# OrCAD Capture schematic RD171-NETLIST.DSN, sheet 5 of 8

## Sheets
5 4: size A3
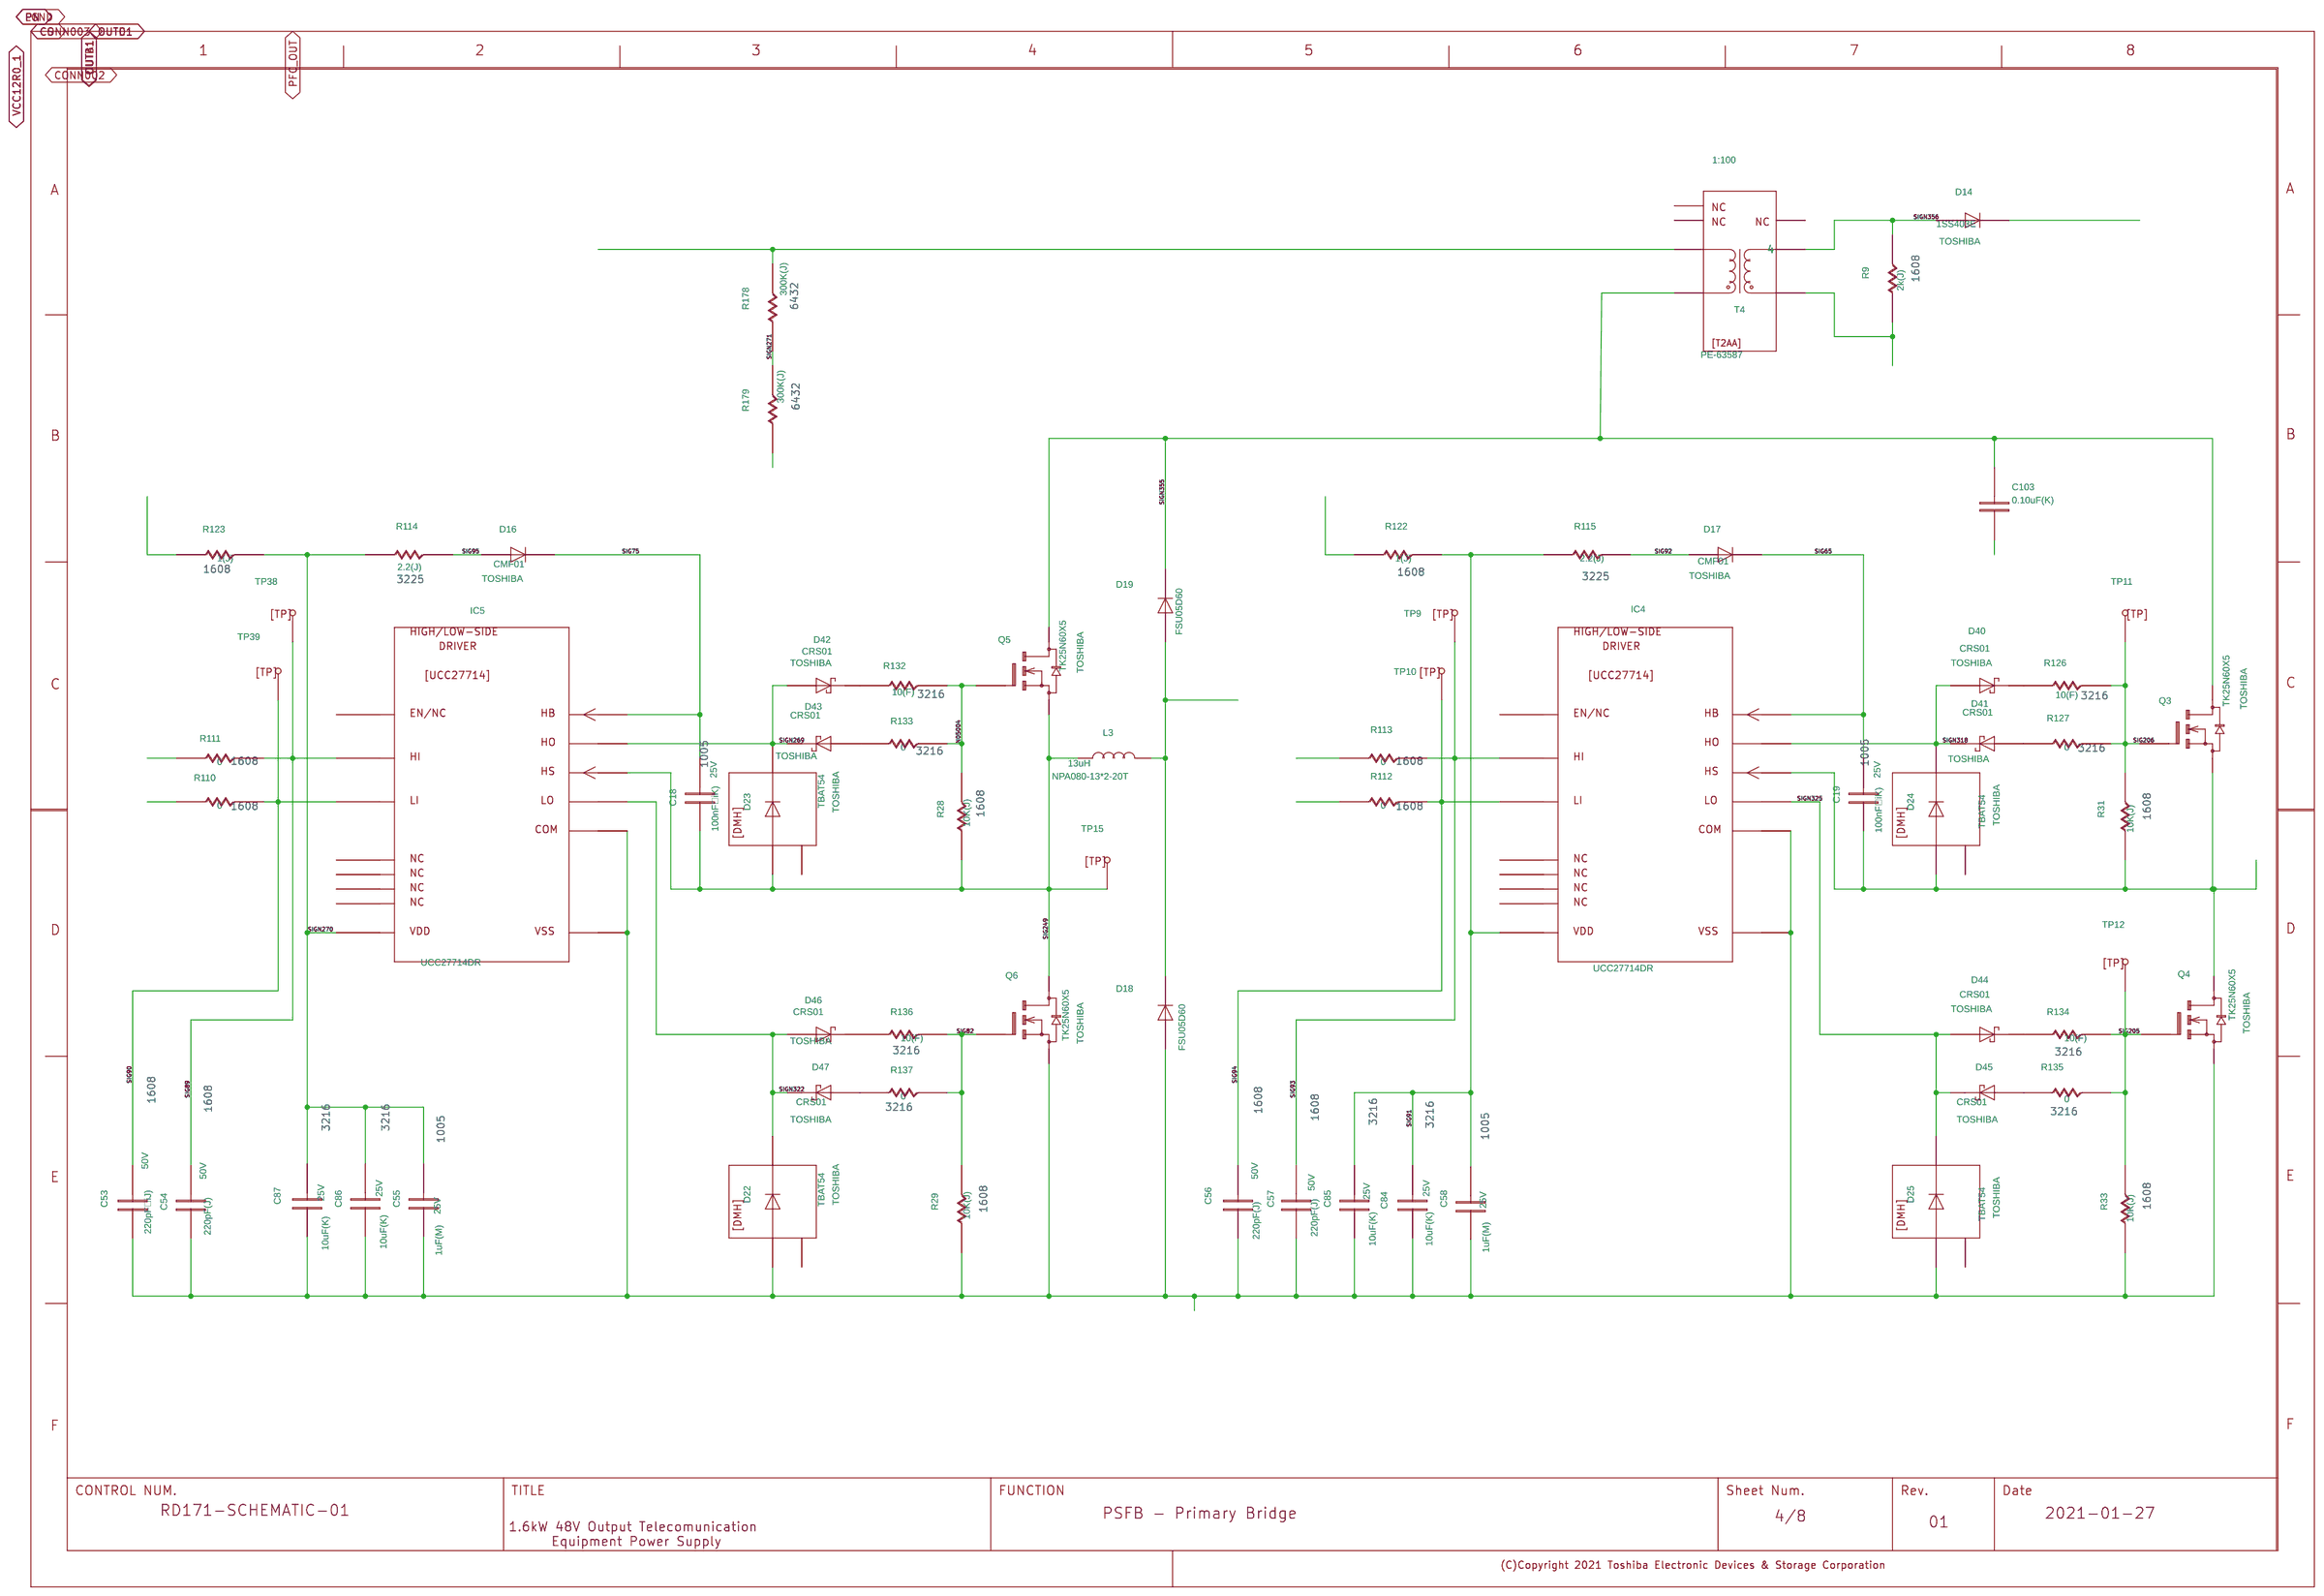
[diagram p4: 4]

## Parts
C18  100nF
C19  100nF
C53  220pF
C54  220pF
C55  1uF
C56  220pF
C57  220pF
C58  1uF
C84  10uF
C85  10uF
C86  10uF
C87  10uF
C103  0.10ƒÊF
D14  D14  [1SS403E]
D16  D16  [CMF01]
D17  D17  [CMF01]
D18  D1  [TRS8E65F]
D19  D1  [TRS8E65F]
D22  D22  [TBAT54]
D23  D23  [TBAT54]
D24  D24  [TBAT54]
D25  D25  [TBAT54]
D40  D40  [CRS01]
D41  D41  [CRS01]
D42  D42  [CRS01]
D43  D43  [CRS01]
D44  D44  [CRS01]
D45  D45  [CRS01]
D46  D46  [CRS01]
D47  D47  [CRS01]
IC4  IC4  [UCC27714DR]
IC5  IC5  [UCC27714DR]
L3  8.4uH  [NPA080-14*2-16T]
Q3  Q3  [TK25N60X5]
Q4  Q4  [TK25N60X5]
Q5  Q5  [TK25N60X5]
Q6  Q6  [TK25N60X5]
R9  2k
R28  10k
R29  10k
R31  10k
R33  10k
R110  0
R111  0
R112  0
R113  0
R114  2.2
R115  2.2
R122  1
R123  1
R126  10
R127  0
R132  10
R133  0
R134  10
R135  0
R136  10
R137  0
R178  300k
R179  300k
T4  1:100  [PE-63587NL]
TP9  TP9  [HK-2-S]
TP10  TP10  [HK-2-S]
TP11  TP11  [HK-2-S]
TP12  TP12  [HK-2-S]
TP15  TP15  [HK-2-S]
TP38  TP38  [HK-2-S]
TP39  TP39  [HK-2-S]
U?#4  WAKU_DEF100

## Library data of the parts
C18 = C: ADSCNVFLAG: ON; ADSCOMPONENTNAME: C_1005; ADSMODELNAME: s_C1005JB1C224KT; CAPACITANCETOLE: K; CDMASTERCADCELG: KC0005; CHIPSIZE: 1005; COMP: PRT_52; COMPONENTNAME: C_C.Normal_package; FNLEADFREETHET1GT2GMCTH1: N_N_N; FUNCTION: C_C.Normal_package; GCOUNT: 1; ICX_PART_MODEL: CON_220N; INSTANCENAME: INS4234; MAKER: TDK; MAXGCOUNT: 1; NOMINALCAPACITA: 220n; OUMECLASSIFICATION: ƒZƒ‰ƒ~ƒbƒNƒRƒ“ƒfƒ“ƒT; OUMEMAKER: TDK ‚s‚c‚j; OUMEMAKERKATAMEI: C1005JB1C224KT; PARTNAME: Chip1005_GS_2; QUADMODEL: CON_220N; RATEDVOLTAGE: 16; SIZECODESMD: 1005; SQ_PART_MODEL: CON_220N; TEMPCHARACTERI2: B; VAL1: 100nFiK); VAL2: 25V; VAL3: C1005X7R1E104K050BB
C19 = C: ADSMODELNAME: s_C1005JB1C224KT; CAPACITANCETOLE: K; CDMASTERCADCELG: KC0005; CHIPSIZE: 1005; COMP: PRT_52; COMPONENTNAME: C_C.Normal_package; FNLEADFREETHET1GT2GMCTH1: N_N_N; FUNCTION: C_C.Normal_package; GCOUNT: 1; INSTANCENAME: INS4196; MAKER: TDK; MAXGCOUNT: 1; NOMINALCAPACITA: 220n; OUMECLASSIFICATION: ƒZƒ‰ƒ~ƒbƒNƒRƒ“ƒfƒ“ƒT; OUMEMAKER: TDK ‚s‚c‚j; OUMEMAKERKATAMEI: C1005JB1C224KT; PARTNAME: Chip1005_GS_2; QUADMODEL: CON_220N; RATEDVOLTAGE: 16; SIZECODESMD: 1005; TEMPCHARACTERI2: B; VAL1: 100nFiK); VAL2: 25V; VAL3: C1005X7R1E104K050BB
C53 = C: ADSMODELNAME: s_GCM1885C1H221JA16D; CAPACITANCETOLE: J; CDMASTERCADCELG: KC0008; CHIPSIZE: 1608; COMP: PRT_48; COMPONENTNAME: C_C.Normal_package; FNLEADFREETHET1GT2GMCTH1: N_N_N; FUNCTION: C_C.Normal_package; GCOUNT: 1; INSTANCENAME: INS4564; MAKER: MURATA; MAXGCOUNT: 1; NOMINALCAPACITA: 220p; OUMECLASSIFICATION: ƒZƒ‰ƒ~ƒbƒNƒRƒ“ƒfƒ“ƒT; OUMEMAKER: MRT ºc»ì; OUMEMAKERKATAMEI: GCM1885C1H221JA16D; PARTNAME: Chip1608_GS_1; PMPRODUCTSTYPEG: DME; QUADMODEL: CON_220P; RATEDVOLTAGE: 50; SIZECODESMD: 1608; VAL1: 220pFiJ); VAL2: 50V; VAL3: GRM1885C1H221JA01D
C54 = C: ADSMODELNAME: s_GCM1885C1H221JA16D; CAPACITANCETOLE: J; CDMASTERCADCELG: KC0008; CHIPSIZE: 1608; COMP: PRT_48; COMPONENTNAME: C_C.Normal_package; FNLEADFREETHET1GT2GMCTH1: N_N_N; FUNCTION: C_C.Normal_package; GCOUNT: 1; INSTANCENAME: INS4576; MAKER: MURATA; MAXGCOUNT: 1; NOMINALCAPACITA: 220p; OUMECLASSIFICATION: ƒZƒ‰ƒ~ƒbƒNƒRƒ“ƒfƒ“ƒT; OUMEMAKER: MRT ºc»ì; OUMEMAKERKATAMEI: GCM1885C1H221JA16D; PARTNAME: Chip1608_GS_1; PMPRODUCTSTYPEG: DME; QUADMODEL: CON_220P; RATEDVOLTAGE: 50; SIZECODESMD: 1608; VAL1: 220pF(J); VAL2: 50V; VAL3: GRM1885C1H221JA01D
C55 = C: ADSCNVFLAG: ON; ADSCOMPONENTNAME: C_1005; ADSMODELNAME: s_GRM155R61A225KE95D; CAPACITANCETOLE: K; CDMASTERCADCELG: KC0005; CHIPSIZE: 1005; COMP: PRT_52; COMPONENTNAME: C_C.Normal_package; FNLEADFREETHET1GT2GMCTH1: N_N_N; FUNCTION: C_C.Normal_package; GCOUNT: 1; ICX_PART_MODEL: CON_2.2U; INSTANCENAME: INS4176; MAKER: TDK; MAXGCOUNT: 1; NOMINALCAPACITA: 2.2u; OUMECLASSIFICATION: ƒZƒ‰ƒ~ƒbƒNƒRƒ“ƒfƒ“ƒT; OUMEMAKER: MRT ºc»ì; OUMEMAKERKATAMEI: GRM155R61A225KE95D; PARTNAME: Chip1005_GS_2; PMPRODUCTSTYPEG: HD1; QUADMODEL: CON_2.2U; RATEDVOLTAGE: 10; SIZECODESMD: 1005; SQ_PART_MODEL: CON_2.2U; VAL1: 1uF(M); VAL2: 25V; VAL3: C1005X5R1E105M050BC
C56 = C: ADSMODELNAME: s_GCM1885C1H221JA16D; CAPACITANCETOLE: J; CDMASTERCADCELG: KC0008; CHIPSIZE: 1608; COMP: PRT_48; COMPONENTNAME: C_C.Normal_package; FNLEADFREETHET1GT2GMCTH1: N_N_N; FUNCTION: C_C.Normal_package; GCOUNT: 1; INSTANCENAME: INS4452; MAKER: MURATA; MAXGCOUNT: 1; NOMINALCAPACITA: 220p; OUMECLASSIFICATION: ƒZƒ‰ƒ~ƒbƒNƒRƒ“ƒfƒ“ƒT; OUMEMAKER: MRT ºc»ì; OUMEMAKERKATAMEI: GCM1885C1H221JA16D; PARTNAME: Chip1608_GS_1; PMPRODUCTSTYPEG: DME; QUADMODEL: CON_220P; RATEDVOLTAGE: 50; SIZECODESMD: 1608; VAL1: 220pF(J); VAL2: 50V; VAL3: GRM1885C1H221JA01D
C57 = C: ADSMODELNAME: s_GCM1885C1H221JA16D; CAPACITANCETOLE: J; CDMASTERCADCELG: KC0008; CHIPSIZE: 1608; COMP: PRT_48; COMPONENTNAME: C_C.Normal_package; FNLEADFREETHET1GT2GMCTH1: N_N_N; FUNCTION: C_C.Normal_package; GCOUNT: 1; INSTANCENAME: INS4440; MAKER: MURATA; MAXGCOUNT: 1; NOMINALCAPACITA: 220p; OUMECLASSIFICATION: ƒZƒ‰ƒ~ƒbƒNƒRƒ“ƒfƒ“ƒT; OUMEMAKER: MRT ºc»ì; OUMEMAKERKATAMEI: GCM1885C1H221JA16D; PARTNAME: Chip1608_GS_1; PMPRODUCTSTYPEG: DME; QUADMODEL: CON_220P; RATEDVOLTAGE: 50; SIZECODESMD: 1608; VAL1: 220pF(J); VAL2: 50V; VAL3: GRM1885C1H221JA01D
C58 = C: ADSMODELNAME: s_GRM155R61A225KE95D; CAPACITANCETOLE: K; CDMASTERCADCELG: KC0005; CHIPSIZE: 1005; COMP: PRT_52; COMPONENTNAME: C_C.Normal_package; FNLEADFREETHET1GT2GMCTH1: N_N_N; FUNCTION: C_C.Normal_package; GCOUNT: 1; INSTANCENAME: INS4186; MAKER: TDK; MAXGCOUNT: 1; NOMINALCAPACITA: 2.2u; OUMECLASSIFICATION: ƒZƒ‰ƒ~ƒbƒNƒRƒ“ƒfƒ“ƒT; OUMEMAKER: MRT ºc»ì; OUMEMAKERKATAMEI: GRM155R61A225KE95D; PARTNAME: Chip1005_GS_2; PMPRODUCTSTYPEG: HD1; QUADMODEL: CON_2.2U; RATEDVOLTAGE: 10; SIZECODESMD: 1005; VAL1: 1uF(M); VAL2: 25V; VAL3: C1005X5R1E105M050BC
C84 = C: ADSMODELNAME: s_TMK316LD106KL_T; CAPACITANCETOLE: K; CDMASTERCADCELG: KC0014; CHIPSIZE: 3216; COMP: PRT_46; COMPONENTNAME: C_C.Normal_package; FNLEADFREETHET1GT2GMCTH1: N_N_N; FUNCTION: C_C.Normal_package; GCOUNT: 1; INSTANCENAME: INS4474; MAKER: TAIYO YUDEN; MAXGCOUNT: 1; NOMINALCAPACITA: 10u; OUMECLASSIFICATION: ƒZƒ‰ƒ~ƒbƒNƒRƒ“ƒfƒ“ƒT; OUMEMAKER: TYD ‘¾—z—U“d; OUMEMAKERKATAMEI: TMK316LD106KL-T; PARTNAME: Chip3216_GS_1; QUADMODEL: CON_10U; RATEDVOLTAGE: 25; SIZECODESMD: 3216; VAL1: 10uF(K); VAL2: 25V; VAL3: TMK316BJ106KL-T
C85 = C: ADSMODELNAME: s_TMK316LD106KL_T; CAPACITANCETOLE: K; CDMASTERCADCELG: KC0014; CHIPSIZE: 3216; COMP: PRT_46; COMPONENTNAME: C_C.Normal_package; FNLEADFREETHET1GT2GMCTH1: N_N_N; FUNCTION: C_C.Normal_package; GCOUNT: 1; INSTANCENAME: INS4464; MAKER: TAIYO YUDEN; MAXGCOUNT: 1; NOMINALCAPACITA: 10u; OUMECLASSIFICATION: ƒZƒ‰ƒ~ƒbƒNƒRƒ“ƒfƒ“ƒT; OUMEMAKER: TYD ‘¾—z—U“d; OUMEMAKERKATAMEI: TMK316LD106KL-T; PARTNAME: Chip3216_GS_1; QUADMODEL: CON_10U; RATEDVOLTAGE: 25; SIZECODESMD: 3216; VAL1: 10uF(K); VAL2: 25V; VAL3: TMK316BJ106KL-T
C86 = C: ADSMODELNAME: s_TMK316LD106KL_T; CAPACITANCETOLE: K; CDMASTERCADCELG: KC0014; CHIPSIZE: 3216; COMP: PRT_46; COMPONENTNAME: C_C.Normal_package; FNLEADFREETHET1GT2GMCTH1: N_N_N; FUNCTION: C_C.Normal_package; GCOUNT: 1; INSTANCENAME: INS4598; MAKER: TAIYO YUDEN; MAXGCOUNT: 1; NOMINALCAPACITA: 10u; OUMECLASSIFICATION: ƒZƒ‰ƒ~ƒbƒNƒRƒ“ƒfƒ“ƒT; OUMEMAKER: TYD ‘¾—z—U“d; OUMEMAKERKATAMEI: TMK316LD106KL-T; PARTNAME: Chip3216_GS_1; QUADMODEL: CON_10U; RATEDVOLTAGE: 25; SIZECODESMD: 3216; VAL1: 10uF(K); VAL2: 25V; VAL3: TMK316BJ106KL-T
C87 = C: ADSMODELNAME: s_TMK316LD106KL_T; CAPACITANCETOLE: K; CDMASTERCADCELG: KC0014; CHIPSIZE: 3216; COMP: PRT_46; COMPONENTNAME: C_C.Normal_package; FNLEADFREETHET1GT2GMCTH1: N_N_N; FUNCTION: C_C.Normal_package; GCOUNT: 1; INSTANCENAME: INS4588; MAKER: TAIYO YUDEN; MAXGCOUNT: 1; NOMINALCAPACITA: 10u; OUMECLASSIFICATION: ƒZƒ‰ƒ~ƒbƒNƒRƒ“ƒfƒ“ƒT; OUMEMAKER: TYD ‘¾—z—U“d; OUMEMAKERKATAMEI: TMK316LD106KL-T; PARTNAME: Chip3216_GS_1; QUADMODEL: CON_10U; RATEDVOLTAGE: 25; SIZECODESMD: 3216; VAL1: 10uF(K); VAL2: 25V; VAL3: TMK316BJ106KL-T
C103 = RDER72J104K4K1H03B_0: COMPONENTNAME: RDER72J104K4K1H03B_0_RDER72J104K4K1H03B_0; INSTANCENAME: INS16960092; PARTNAME: RDER72J104_MU; VAL1: 0.10uF(K)
D14 = D: ADSMODELNAME: s_1SS352_TPH3_F_1_1E1A; CDMASTERCADCELG: D81022; COMP: PRT_27; COMPONENTNAME: D_D.Normal_package; FNLEADFREETHET1GT2GMCTH1: N_N_N; FORWARDVOLTAGEM: 0; FUNCTION: D_D.Normal_package; GCOUNT: 1; INSTANCENAME: INS4272; MAKER: TOSHIBA; MAXAVERAGEFORWA: 0; MAXGCOUNT: 1; MAXREPETITIVEPE: 0; MAXREVERSEVOLTA: 80; MOUNTINGFORMSMD: SMD; OUMECLASSIFICATION: ¬M_CI[h; OUMEMAKER: TSB “ŒŽÅ; OUMEMAKERKATAMEI: 1SS352(TPH3,F)1-1E1A; PARTNAME: 1SS403E_TS_B; PEAKFORWARDVOLT: 0; REVERSECURRENT: 0; USERCOMPTEXT3: TOSHIBA; ZENERVOLTAGEMAX: 0; ZENERVOLTAGEMIN: 0
D16 = D: ADSMODELNAME: s_MURS220T3G; CDMASTERCADCELG: DD924D; COMP: PRT_14; COMPONENTNAME: D_D.Normal_package; FNLEADFREETHET1GT2GMCTH1: 3_0_N; FORWARDVOLTAGEM: 0; FUNCTION: D_D.Normal_package; GCOUNT: 1; INSTANCENAME: INS4130; MAKER: TOSHIBA; MAXAVERAGEFORWA: 2; MAXGCOUNT: 1; MAXREPETITIVEPE: 200; MAXREVERSEVOLTA: 0; MOUNTINGFORMSMD: SMD; OUMECLASSIFICATION: êÊ®¬fq; OUMEMAKER: ONS IZ~R_N^[; OUMEMAKERKATAMEI: MURS220T3G; PARTNAME: CMF01_TS_B; PEAKFORWARDVOLT: 770m; PMPRODUCTSTYPEG: PJ1; REVERSECURRENT: 50u; USERCOMPTEXT3: TOSHIBA; ZENERVOLTAGEMAX: 0; ZENERVOLTAGEMIN: 0
D17 = D: ADSMODELNAME: s_MURS220T3G; CDMASTERCADCELG: DD924D; COMP: PRT_14; COMPONENTNAME: D_D.Normal_package; FNLEADFREETHET1GT2GMCTH1: 3_0_N; FORWARDVOLTAGEM: 0; FUNCTION: D_D.Normal_package; GCOUNT: 1; INSTANCENAME: INS3988; MAKER: TOSHIBA; MAXAVERAGEFORWA: 2; MAXGCOUNT: 1; MAXREPETITIVEPE: 200; MAXREVERSEVOLTA: 0; MOUNTINGFORMSMD: SMD; OUMECLASSIFICATION: êÊ®¬fq; OUMEMAKER: ONS IZ~R_N^[; OUMEMAKERKATAMEI: MURS220T3G; PARTNAME: CMF01_TS_B; PEAKFORWARDVOLT: 770m; PMPRODUCTSTYPEG: PJ1; REVERSECURRENT: 50u; USERCOMPTEXT3: TOSHIBA; ZENERVOLTAGEMAX: 0; ZENERVOLTAGEMIN: 0
D18 = D: ADSMODELNAME: s_FSU05D60; CDMASTERCADCELG: DCR071; COMP: PRT_12; COMPONENTNAME: D_D.Normal_package; FNLEADFREETHET1GT2GMCTH1: N_N_N; FORWARDVOLTAGEM: 0; FUNCTION: D_D.Normal_package; GCOUNT: 1; INSTANCENAME: INS16993764; MAKER: TOSHIBA; MAXAVERAGEFORWA: 0; MAXGCOUNT: 1; MAXREPETITIVEPE: 0; MAXREVERSEVOLTA: 100; MOUNTINGFORMSMD: DIP; OUMECLASSIFICATION: ¬M_CI[h; OUMEMAKER: ROH [; OUMEMAKERKATAMEI: FSU05D60; PARTNAME: FSU05D60_KC; PEAKFORWARDVOLT: 0; REVERSECURRENT: 0; USERCOMPTEXT3: KYOCERA; VAL3: FSU05D60; ZENERVOLTAGEMAX: 0; ZENERVOLTAGEMIN: 0
D19 = D: ADSMODELNAME: s_FSU05D60; CDMASTERCADCELG: DCR071; COMP: PRT_12; COMPONENTNAME: D_D.Normal_package; FNLEADFREETHET1GT2GMCTH1: N_N_N; FORWARDVOLTAGEM: 0; FUNCTION: D_D.Normal_package; GCOUNT: 1; INSTANCENAME: INS16993843; MAKER: TOSHIBA; MAXAVERAGEFORWA: 0; MAXGCOUNT: 1; MAXREPETITIVEPE: 0; MAXREVERSEVOLTA: 100; MOUNTINGFORMSMD: DIP; OUMECLASSIFICATION: ¬M_CI[h; OUMEMAKER: ROH [; OUMEMAKERKATAMEI: FSU05D60; PARTNAME: FSU05D60_KC; PEAKFORWARDVOLT: 0; REVERSECURRENT: 0; USERCOMPTEXT3: KYOCERA; VAL3: FSU05D60; ZENERVOLTAGEMAX: 0; ZENERVOLTAGEMIN: 0
D22 = DMH: COMP: PRT_25; COMPONENTNAME: DMH_DMH.Normal_package; FUNCTION: DMH_DMH.Normal_package; INSTANCENAME: INS4258; MAKER: TOSHIBA; PARTNAME: TBAT54_TS_B; USERCOMPTEXT3: TOSHIBA
D23 = DMH: COMP: PRT_25; COMPONENTNAME: DMH_DMH.Normal_package; FUNCTION: DMH_DMH.Normal_package; INSTANCENAME: INS4244; MAKER: TOSHIBA; PARTNAME: TBAT54_TS_B; USERCOMPTEXT3: TOSHIBA
D24 = DMH: COMP: PRT_25; COMPONENTNAME: DMH_DMH.Normal_package; FUNCTION: DMH_DMH.Normal_package; INSTANCENAME: INS4220; MAKER: TOSHIBA; PARTNAME: TBAT54_TS_B; USERCOMPTEXT3: TOSHIBA
D25 = DMH: COMP: PRT_25; COMPONENTNAME: DMH_DMH.Normal_package; FUNCTION: DMH_DMH.Normal_package; INSTANCENAME: INS4206; MAKER: TOSHIBA; PARTNAME: TBAT54_TS_B; USERCOMPTEXT3: TOSHIBA
D40 = SBD: COMP: PRT_11; COMPONENTNAME: SBD_SBD.Normal_package; FUNCTION: SBD_SBD.Normal_package; INSTANCENAME: INS4304; MAKER: TOSHIBA; PARTNAME: CRS01_TS_B; USERCOMPTEXT3: TOSHIBA
D41 = SBD: COMP: PRT_11; COMPONENTNAME: SBD_SBD.Normal_package; FUNCTION: SBD_SBD.Normal_package; INSTANCENAME: INS4316; MAKER: TOSHIBA; PARTNAME: CRS01_TS_B; USERCOMPTEXT3: TOSHIBA
D42 = SBD: COMP: PRT_11; COMPONENTNAME: SBD_SBD.Normal_package; FUNCTION: SBD_SBD.Normal_package; INSTANCENAME: INS4348; MAKER: TOSHIBA; PARTNAME: CRS01_TS_B; USERCOMPTEXT3: TOSHIBA
D43 = SBD: COMP: PRT_11; COMPONENTNAME: SBD_SBD.Normal_package; FUNCTION: SBD_SBD.Normal_package; INSTANCENAME: INS4360; MAKER: TOSHIBA; PARTNAME: CRS01_TS_B; USERCOMPTEXT3: TOSHIBA
D44 = SBD: COMP: PRT_11; COMPONENTNAME: SBD_SBD.Normal_package; FUNCTION: SBD_SBD.Normal_package; INSTANCENAME: INS4326; MAKER: TOSHIBA; PARTNAME: CRS01_TS_B; USERCOMPTEXT3: TOSHIBA
D45 = SBD: COMP: PRT_11; COMPONENTNAME: SBD_SBD.Normal_package; FUNCTION: SBD_SBD.Normal_package; INSTANCENAME: INS4338; MAKER: TOSHIBA; PARTNAME: CRS01_TS_B; USERCOMPTEXT3: TOSHIBA
D46 = SBD: COMP: PRT_11; COMPONENTNAME: SBD_SBD.Normal_package; FUNCTION: SBD_SBD.Normal_package; INSTANCENAME: INS4370; MAKER: TOSHIBA; PARTNAME: CRS01_TS_B; USERCOMPTEXT3: TOSHIBA
D47 = SBD: COMP: PRT_11; COMPONENTNAME: SBD_SBD.Normal_package; FUNCTION: SBD_SBD.Normal_package; INSTANCENAME: INS4382; MAKER: TOSHIBA; PARTNAME: CRS01_TS_B; USERCOMPTEXT3: TOSHIBA
IC4 = L27714: COMP: PRT_58; COMPONENTNAME: L27714_L27714.Normal_package; FUNCTION: L27714_L27714.Normal_package; INSTANCENAME: INS3954; MAKER: TEXAS; PARTNAME: UCC27714D_TI; SAVECOUNT: 1; UPDATEDATE: 2020/07/08; UPDATETIME: 16:40:04
IC5 = L27714: COMP: PRT_58; COMPONENTNAME: L27714_L27714.Normal_package; FUNCTION: L27714_L27714.Normal_package; INSTANCENAME: INS4072; MAKER: TEXAS; PARTNAME: UCC27714D_TI; SAVECOUNT: 1; UPDATEDATE: 2020/07/08; UPDATETIME: 16:40:04
L3 = L: COMP: PRT_41; COMPONENTNAME: L_L.Normal_package; FUNCTION: L_L.Normal_package; GCOUNT: 1; INDUCTANCEMAX: 0; INDUCTANCEMIN: 0; INSTANCENAME: INS16989329; MAKER: FURUKAWA; MAXGCOUNT: 1; MOUNTINGFORMSMD: DIP; NOMINALINDUCTA1: 8.4u; NOMINALINDUCTA2: K; PARTNAME: NPA080-13x2-20T_GS; VAL1: 13uH; VAL2: (Rated Current/Idc=0A); VAL3: NPA080-13*2-20T
Q3 = MFNF_3: COMP: PRT_9; COMPONENTNAME: MFNF_3_MFNF_3; INSTANCENAME: INS4010; MAKER: TOSHIBA; PARTNAME: TK25N60X5_TS; USERCOMPTEXT3: TOSHIBA
Q4 = MFNF_3: COMP: PRT_9; COMPONENTNAME: MFNF_3_MFNF_3; INSTANCENAME: INS4034; MAKER: TOSHIBA; PARTNAME: TK25N60X5_TS; USERCOMPTEXT3: TOSHIBA
Q5 = MFNF_3: COMP: PRT_9; COMPONENTNAME: MFNF_3_MFNF_3; INSTANCENAME: INS4116; MAKER: TOSHIBA; PARTNAME: TK25N60X5_TS; USERCOMPTEXT3: TOSHIBA
Q6 = MFNF_3: COMP: PRT_9; COMPONENTNAME: MFNF_3_MFNF_3; INSTANCENAME: INS4152; MAKER: TOSHIBA; PARTNAME: TK25N60X5_TS; USERCOMPTEXT3: TOSHIBA
R9 = R: ADSCNVFLAG: ON; ADSCOMPONENTNAME: R_3216; ADSMODELNAME: s_RK73H2BTTD4871F; CDMASTERCADCELG: DR901A; CHIPSIZE: 1608; COMP: PRT_8; COMPONENTNAME: R_R.Normal_package; FNLEADFREETHET1GT2GMCTH1: 3_1_N; FUNCTION: R_R.Normal_package; GCOUNT: 1; ICX_PART_MODEL: RES_4.87K; INSTANCENAME: INS4166; MAKER: KOA; MAXGCOUNT: 1; MOUNTINGFORMSMD: SMD; NOMINALRESISTAN: 4.87K; OUMECLASSIFICATION: \ÊÀpÅèïRí; OUMEMAKER: KOA R[A; OUMEMAKERKATAMEI: RK73H2BTTD4871F; PARTNAME: Chip1608_GS_1; POWERRATING: 250m; QUADMODEL: RES_4.87K; RESISTANCETOLER: F; SIZECODESMD: 3216; SQ_PART_MODEL: RES_4.87K; VAL1: 2k(J); VAL2: 100mW,}5%; VAL3: RK73B1JTTD202J
R28 = R: ADSMODELNAME: s_RK73B1JTTD103J@@; CDMASTERCADCELG: KC0133; CHIPSIZE: 1608; COMP: PRT_8; COMPONENTNAME: R_R.Normal_package; FNLEADFREETHET1GT2GMCTH1: N_N_N; FUNCTION: R_R.Normal_package; GCOUNT: 1; INSTANCENAME: INS4106; MAKER: KOA; MAXGCOUNT: 1; MOUNTINGFORMSMD: SMD; NOMINALRESISTAN: 10K; OUMECLASSIFICATION: \ÊÀpÅèïRí; OUMEMAKER: KOA R[A; OUMEMAKERKATAMEI: RK73B1JTTD103J@@; PARTNAME: Chip1608_GS_1; POWERRATING: 100m; QUADMODEL: RES_10K; RESISTANCETOLER: J; SIZECODESMD: 1608; VAL1: 10K(J); VAL2: 100mW,}5%; VAL3: RK73B1JTTD103J
R29 = R: ADSMODELNAME: s_RK73B1JTTD103J@@; CDMASTERCADCELG: KC0133; CHIPSIZE: 1608; COMP: PRT_8; COMPONENTNAME: R_R.Normal_package; FNLEADFREETHET1GT2GMCTH1: N_N_N; FUNCTION: R_R.Normal_package; GCOUNT: 1; INSTANCENAME: INS4142; MAKER: KOA; MAXGCOUNT: 1; MOUNTINGFORMSMD: SMD; NOMINALRESISTAN: 10K; OUMECLASSIFICATION: \ÊÀpÅèïRí; OUMEMAKER: KOA R[A; OUMEMAKERKATAMEI: RK73B1JTTD103J@@; PARTNAME: Chip1608_GS_1; POWERRATING: 100m; QUADMODEL: RES_10K; RESISTANCETOLER: J; SIZECODESMD: 1608; VAL1: 10K(J); VAL2: 100mW,}5%; VAL3: RK73B1JTTD103J
R31 = R: ADSMODELNAME: s_RK73B1JTTD103J@@; CDMASTERCADCELG: KC0133; CHIPSIZE: 1608; COMP: PRT_8; COMPONENTNAME: R_R.Normal_package; FNLEADFREETHET1GT2GMCTH1: N_N_N; FUNCTION: R_R.Normal_package; GCOUNT: 1; INSTANCENAME: INS4000; MAKER: KOA; MAXGCOUNT: 1; MOUNTINGFORMSMD: SMD; NOMINALRESISTAN: 10K; OUMECLASSIFICATION: \ÊÀpÅèïRí; OUMEMAKER: KOA R[A; OUMEMAKERKATAMEI: RK73B1JTTD103J@@; PARTNAME: Chip1608_GS_1; POWERRATING: 100m; QUADMODEL: RES_10K; RESISTANCETOLER: J; SIZECODESMD: 1608; VAL1: 10K(J); VAL2: 100mW,}5%; VAL3: RK73B1JTTD103J
R33 = R: ADSMODELNAME: s_RK73B1JTTD103J@@; CDMASTERCADCELG: KC0133; CHIPSIZE: 1608; COMP: PRT_8; COMPONENTNAME: R_R.Normal_package; FNLEADFREETHET1GT2GMCTH1: N_N_N; FUNCTION: R_R.Normal_package; GCOUNT: 1; INSTANCENAME: INS4024; MAKER: KOA; MAXGCOUNT: 1; MOUNTINGFORMSMD: SMD; NOMINALRESISTAN: 10K; OUMECLASSIFICATION: \ÊÀpÅèïRí; OUMEMAKER: KOA R[A; OUMEMAKERKATAMEI: RK73B1JTTD103J@@; PARTNAME: Chip1608_GS_1; POWERRATING: 100m; QUADMODEL: RES_10K; RESISTANCETOLER: J; SIZECODESMD: 1608; VAL1: 10K(J); VAL2: 100mW,}5%; VAL3: RK73B1JTTD103J
R110 = R: ADSMODELNAME: s_RK73Z1JTTD; CDMASTERCADCELG: KCK0203; CHIPSIZE: 1608; COMP: PRT_8; COMPONENTNAME: R_R.Normal_package; FNLEADFREETHET1GT2GMCTH1: 3_2_N; FUNCTION: R_R.Normal_package; GCOUNT: 1; INSTANCENAME: INS4534; MAKER: KOA; MAXGCOUNT: 1; MOUNTINGFORMSMD: SMD; OUMECLASSIFICATION: \ÊÀpÅèïRí; OUMEMAKER: KOA R[A; OUMEMAKERKATAMEI: RK73Z1JTTD; PARTNAME: Chip1608_GS_1; PMPRODUCTSTYPEG: DME-HD1-PC1; POWERRATING: 100m; QUADMODEL: RES_0; RESISTANCETOLER: X; SIZECODESMD: 1608; VAL2: 100mW; VAL3: RK73Z1JTTD
R111 = R: ADSMODELNAME: s_RK73Z1JTTD; CDMASTERCADCELG: KCK0203; CHIPSIZE: 1608; COMP: PRT_8; COMPONENTNAME: R_R.Normal_package; FNLEADFREETHET1GT2GMCTH1: 3_2_N; FUNCTION: R_R.Normal_package; GCOUNT: 1; INSTANCENAME: INS4544; MAKER: KOA; MAXGCOUNT: 1; MOUNTINGFORMSMD: SMD; OUMECLASSIFICATION: \ÊÀpÅèïRí; OUMEMAKER: KOA R[A; OUMEMAKERKATAMEI: RK73Z1JTTD; PARTNAME: Chip1608_GS_1; PMPRODUCTSTYPEG: DME-HD1-PC1; POWERRATING: 100m; QUADMODEL: RES_0; RESISTANCETOLER: X; SIZECODESMD: 1608; VAL2: 100mW; VAL3: RK73Z1JTTD
R112 = R: ADSMODELNAME: s_RK73Z1JTTD; CDMASTERCADCELG: KCK0203; CHIPSIZE: 1608; COMP: PRT_8; COMPONENTNAME: R_R.Normal_package; FNLEADFREETHET1GT2GMCTH1: 3_2_N; FUNCTION: R_R.Normal_package; GCOUNT: 1; INSTANCENAME: INS4430; MAKER: KOA; MAXGCOUNT: 1; MOUNTINGFORMSMD: SMD; OUMECLASSIFICATION: \ÊÀpÅèïRí; OUMEMAKER: KOA R[A; OUMEMAKERKATAMEI: RK73Z1JTTD; PARTNAME: Chip1608_GS_1; PMPRODUCTSTYPEG: DME-HD1-PC1; POWERRATING: 100m; QUADMODEL: RES_0; RESISTANCETOLER: X; SIZECODESMD: 1608; VAL2: 100mW; VAL3: RK73Z1JTTD
R113 = R: ADSMODELNAME: s_RK73Z1JTTD; CDMASTERCADCELG: KCK0203; CHIPSIZE: 1608; COMP: PRT_8; COMPONENTNAME: R_R.Normal_package; FNLEADFREETHET1GT2GMCTH1: 3_2_N; FUNCTION: R_R.Normal_package; GCOUNT: 1; INSTANCENAME: INS4420; MAKER: KOA; MAXGCOUNT: 1; MOUNTINGFORMSMD: SMD; OUMECLASSIFICATION: \ÊÀpÅèïRí; OUMEMAKER: KOA R[A; OUMEMAKERKATAMEI: RK73Z1JTTD; PARTNAME: Chip1608_GS_1; PMPRODUCTSTYPEG: DME-HD1-PC1; POWERRATING: 100m; QUADMODEL: RES_0; RESISTANCETOLER: X; SIZECODESMD: 1608; VAL2: 100mW; VAL3: RK73Z1JTTD
R114 = R: ADSMODELNAME: s_RK73B2ETTD2R2J; CDMASTERCADCELG: DR903A; CHIPSIZE: 3225; COMP: PRT_23; COMPONENTNAME: R_R.Normal_package; FNLEADFREETHET1GT2GMCTH1: N_N_N; FUNCTION: R_R.Normal_package; GCOUNT: 1; INSTANCENAME: INS4554; MAKER: PANASONIC; MAXGCOUNT: 1; MOUNTINGFORMSMD: SMD; OUMECLASSIFICATION: \ÊÀpÅèïRí; OUMEMAKER: KOA R[A; OUMEMAKERKATAMEI: RK73B2ETTD2R2J; PARTNAME: Chip3225_GS_1; POWERRATING: 500m; QUADMODEL: RES_2.2; RESISTANCETOLER: J; SIZECODESMD: 3225; VAL1: 2.2(J); VAL2: 500mW,}5%; VAL3: ERJ-14YJ2R2U
R115 = R: ADSMODELNAME: s_SG73P2ETTD2R2J; CDMASTERCADCELG: KC0013; CHIPSIZE: 3225; COMP: PRT_23; COMPONENTNAME: R_R.Normal_package; FNLEADFREETHET1GT2GMCTH1: 3_0_N; FUNCTION: R_R.Normal_package; GCOUNT: 1; INSTANCENAME: INS4410; MAKER: PANASONIC; MAXGCOUNT: 1; MOUNTINGFORMSMD: SMD; OUMECLASSIFICATION: \ÊÀpÅèïRí; OUMEMAKER: KOA R[A; OUMEMAKERKATAMEI: SG73P2ETTD2R2J; PARTNAME: Chip3225_GS_1; PMPRODUCTSTYPEG: SV1; POWERRATING: 500m; QUADMODEL: RES_2.2; RESISTANCETOLER: J; SIZECODESMD: 3225; VAL1: 2.2(J); VAL2: 500mW,}5%; VAL3: ERJ-14YJ2R2U
R122 = R: ADSMODELNAME: s_ERJ3RQJ1R0V@@; CDMASTERCADCELG: KC0165; CHIPSIZE: 1608; COMP: PRT_8; COMPONENTNAME: R_R.Normal_package; FNLEADFREETHET1GT2GMCTH1: N_N_N; FUNCTION: R_R.Normal_package; INSTANCENAME: INS4400; MAKER: PANASONIC; MOUNTINGFORMSMD: SMD; OUMECLASSIFICATION: \ÊÀpÅèïRí; OUMEMAKER: NAE pi\jbNGNgjbNfoCX; OUMEMAKERKATAMEI: ERJ3RQJ1R0V@@; PARTNAME: Chip1608_GS_1; PMPRODUCTSTYPEG: DA; POWERRATING: 100m; QUADMODEL: RES_1; RESISTANCETOLER: J; SIZECODESMD: 1608; VAL1: 1(J); VAL2: 100mW,}5%; VAL3: ERJ-3GEYJ1R0V
R123 = R: ADSMODELNAME: s_ERJ3RQJ1R0V@@; CDMASTERCADCELG: KC0165; CHIPSIZE: 1608; COMP: PRT_8; COMPONENTNAME: R_R.Normal_package; FNLEADFREETHET1GT2GMCTH1: N_N_N; FUNCTION: R_R.Normal_package; INSTANCENAME: INS4524; MAKER: PANASONIC; MOUNTINGFORMSMD: SMD; OUMECLASSIFICATION: \ÊÀpÅèïRí; OUMEMAKER: NAE pi\jbNGNgjbNfoCX; OUMEMAKERKATAMEI: ERJ3RQJ1R0V@@; PARTNAME: Chip1608_GS_1; PMPRODUCTSTYPEG: DA; POWERRATING: 100m; QUADMODEL: RES_1; RESISTANCETOLER: J; SIZECODESMD: 1608; VAL1: 1(J); VAL2: 100mW,}5%; VAL3: ERJ-3GEYJ1R0V
R126 = R: ADSMODELNAME: s_RL1632H_R001_JN; CDMASTERCADCELG: KC0020; CHIPSIZE: 3216; COMP: PRT_5; COMPONENTNAME: R_R.Normal_package; FNLEADFREETHET1GT2GMCTH1: N_N_N; FUNCTION: R_R.Normal_package; GCOUNT: 1; INSTANCENAME: INS4484; MAKER: KOA; MAXGCOUNT: 1; MOUNTINGFORMSMD: SMD; NOMINALRESISTAN: 1m; OUMECLASSIFICATION: \ÊÀpÅèïRí; OUMEMAKER: SSM iHÆ; OUMEMAKERKATAMEI: RL1632H-R001-JN; PARTNAME: Chip3216_GS_1; POWERRATING: 500m; QUADMODEL: RES_1M; RESISTANCETOLER: J; SIZECODESMD: 3216; VAL1: 10(F); VAL2: 500mW; VAL3: RK73Z2BTTD
R127 = R: ADSMODELNAME: s_RL1632H_R001_JN; CDMASTERCADCELG: KC0020; CHIPSIZE: 3216; COMP: PRT_5; COMPONENTNAME: R_R.Normal_package; FNLEADFREETHET1GT2GMCTH1: N_N_N; FUNCTION: R_R.Normal_package; GCOUNT: 1; INSTANCENAME: INS4494; MAKER: KOA; MAXGCOUNT: 1; MOUNTINGFORMSMD: SMD; NOMINALRESISTAN: 1m; OUMECLASSIFICATION: \ÊÀpÅèïRí; OUMEMAKER: SSM iHÆ; OUMEMAKERKATAMEI: RL1632H-R001-JN; PARTNAME: Chip3216_GS_1; POWERRATING: 500m; QUADMODEL: RES_1M; RESISTANCETOLER: J; SIZECODESMD: 3216; VAL2: 500mW; VAL3: RK73Z2BTTD
R132 = R: ADSMODELNAME: s_RL1632H_R001_JN; CDMASTERCADCELG: KC0020; CHIPSIZE: 3216; COMP: PRT_5; COMPONENTNAME: R_R.Normal_package; FNLEADFREETHET1GT2GMCTH1: N_N_N; FUNCTION: R_R.Normal_package; GCOUNT: 1; INSTANCENAME: INS4608; MAKER: KOA; MAXGCOUNT: 1; MOUNTINGFORMSMD: SMD; NOMINALRESISTAN: 1m; OUMECLASSIFICATION: \ÊÀpÅèïRí; OUMEMAKER: SSM iHÆ; OUMEMAKERKATAMEI: RL1632H-R001-JN; PARTNAME: Chip3216_GS_1; POWERRATING: 500m; QUADMODEL: RES_1M; RESISTANCETOLER: J; SIZECODESMD: 3216; VAL1: 10(F); VAL2: 500mW; VAL3: RK73Z2BTTD
R133 = R: ADSMODELNAME: s_RL1632H_R001_JN; CDMASTERCADCELG: KC0020; CHIPSIZE: 3216; COMP: PRT_5; COMPONENTNAME: R_R.Normal_package; FNLEADFREETHET1GT2GMCTH1: N_N_N; FUNCTION: R_R.Normal_package; GCOUNT: 1; INSTANCENAME: INS4618; MAKER: KOA; MAXGCOUNT: 1; MOUNTINGFORMSMD: SMD; NOMINALRESISTAN: 1m; OUMECLASSIFICATION: \ÊÀpÅèïRí; OUMEMAKER: SSM iHÆ; OUMEMAKERKATAMEI: RL1632H-R001-JN; PARTNAME: Chip3216_GS_1; POWERRATING: 500m; QUADMODEL: RES_1M; RESISTANCETOLER: J; SIZECODESMD: 3216; VAL2: 500mW; VAL3: RK73Z2BTTD
R134 = R: ADSMODELNAME: s_RL1632H_R001_JN; CDMASTERCADCELG: KC0020; CHIPSIZE: 3216; COMP: PRT_5; COMPONENTNAME: R_R.Normal_package; FNLEADFREETHET1GT2GMCTH1: N_N_N; FUNCTION: R_R.Normal_package; GCOUNT: 1; INSTANCENAME: INS4504; MAKER: KOA; MAXGCOUNT: 1; MOUNTINGFORMSMD: SMD; NOMINALRESISTAN: 1m; OUMECLASSIFICATION: \ÊÀpÅèïRí; OUMEMAKER: SSM iHÆ; OUMEMAKERKATAMEI: RL1632H-R001-JN; PARTNAME: Chip3216_GS_1; POWERRATING: 500m; QUADMODEL: RES_1M; RESISTANCETOLER: J; SIZECODESMD: 3216; VAL1: 10(F); VAL2: 500mW; VAL3: RK73Z2BTTD
R135 = R: ADSMODELNAME: s_RL1632H_R001_JN; CDMASTERCADCELG: KC0020; CHIPSIZE: 3216; COMP: PRT_5; COMPONENTNAME: R_R.Normal_package; FNLEADFREETHET1GT2GMCTH1: N_N_N; FUNCTION: R_R.Normal_package; GCOUNT: 1; INSTANCENAME: INS4514; MAKER: KOA; MAXGCOUNT: 1; MOUNTINGFORMSMD: SMD; NOMINALRESISTAN: 1m; OUMECLASSIFICATION: \ÊÀpÅèïRí; OUMEMAKER: SSM iHÆ; OUMEMAKERKATAMEI: RL1632H-R001-JN; PARTNAME: Chip3216_GS_1; POWERRATING: 500m; QUADMODEL: RES_1M; RESISTANCETOLER: J; SIZECODESMD: 3216; VAL2: 500mW; VAL3: RK73Z2BTTD
R136 = R: ADSMODELNAME: s_RL1632H_R001_JN; CDMASTERCADCELG: KC0020; CHIPSIZE: 3216; COMP: PRT_5; COMPONENTNAME: R_R.Normal_package; FNLEADFREETHET1GT2GMCTH1: N_N_N; FUNCTION: R_R.Normal_package; GCOUNT: 1; INSTANCENAME: INS4628; MAKER: KOA; MAXGCOUNT: 1; MOUNTINGFORMSMD: SMD; NOMINALRESISTAN: 1m; OUMECLASSIFICATION: \ÊÀpÅèïRí; OUMEMAKER: SSM iHÆ; OUMEMAKERKATAMEI: RL1632H-R001-JN; PARTNAME: Chip3216_GS_1; POWERRATING: 500m; QUADMODEL: RES_1M; RESISTANCETOLER: J; SIZECODESMD: 3216; VAL1: 10(F); VAL2: 500mW; VAL3: RK73Z2BTTD
R137 = R: ADSMODELNAME: s_RL1632H_R001_JN; CDMASTERCADCELG: KC0020; CHIPSIZE: 3216; COMP: PRT_5; COMPONENTNAME: R_R.Normal_package; FNLEADFREETHET1GT2GMCTH1: N_N_N; FUNCTION: R_R.Normal_package; GCOUNT: 1; INSTANCENAME: INS4638; MAKER: KOA; MAXGCOUNT: 1; MOUNTINGFORMSMD: SMD; NOMINALRESISTAN: 1m; OUMECLASSIFICATION: \ÊÀpÅèïRí; OUMEMAKER: SSM iHÆ; OUMEMAKERKATAMEI: RL1632H-R001-JN; PARTNAME: Chip3216_GS_1; POWERRATING: 500m; QUADMODEL: RES_1M; RESISTANCETOLER: J; SIZECODESMD: 3216; VAL2: 500mW; VAL3: RK73Z2BTTD
R178 = R: CHIPSIZE: 6432; COMP: PRT_43; COMPONENTNAME: R_R.Normal_package; FUNCTION: R_R.Normal_package; INSTANCENAME: INS4284; MAKER: VISHAY; PARTNAME: Chip6432_GS; VAL1: 300K(J); VAL2: 1W,}5%; VAL3: CRCW2512300KJNEG
R179 = R: CHIPSIZE: 6432; COMP: PRT_43; COMPONENTNAME: R_R.Normal_package; FUNCTION: R_R.Normal_package; INSTANCENAME: INS4294; MAKER: VISHAY; PARTNAME: Chip6432_GS; VAL1: 300K(J); VAL2: 1W,}5%; VAL3: CRCW2512300KJNEG
T4 = T2AA: COMP: PRT_65; COMPONENTNAME: T2AA_T2AA.Normal_package; FUNCTION: T2AA_T2AA.Normal_package; GCOUNT: 1; INDUCTANCEMAX: 0; INDUCTANCEMIN: 0; INSTANCENAME: INS4720; MAKER: PULSE; MAXGCOUNT: 1; MOUNTINGFORMSMD: DIP; NOMINALINDUCTA1: 140u; NOMINALINDUCTA2: X; PARTNAME: PE-63587NL_PU; VAL3: PE-63587
TP9 = TP: COMP: PRT_44; COMPONENTNAME: TP_TP.Normal_package; FUNCTION: TP_TP.Normal_package; ID: OUTC1; INSTANCENAME: INS4648; MAKER: MAC8; PARTNAME: HK-2_M8
TP10 = TP: COMP: PRT_44; COMPONENTNAME: TP_TP.Normal_package; FUNCTION: TP_TP.Normal_package; ID: OUTD1; INSTANCENAME: INS4656; MAKER: MAC8; PARTNAME: HK-2_M8
TP11 = TP: COMP: PRT_44; COMPONENTNAME: TP_TP.Normal_package; FUNCTION: TP_TP.Normal_package; ID: Q3-G; INSTANCENAME: INS4664; MAKER: MAC8; PARTNAME: HK-2_M8
TP12 = TP: COMP: PRT_44; COMPONENTNAME: TP_TP.Normal_package; FUNCTION: TP_TP.Normal_package; ID: Q4-G; INSTANCENAME: INS4672; MAKER: MAC8; PARTNAME: HK-2_M8
TP15 = TP: COMP: PRT_44; COMPONENTNAME: TP_TP.Normal_package; FUNCTION: TP_TP.Normal_package; ID: SW; INSTANCENAME: INS4696; MAKER: MAC8; PARTNAME: HK-2_M8
TP38 = TP: COMP: PRT_44; COMPONENTNAME: TP_TP.Normal_package; FUNCTION: TP_TP.Normal_package; ID: OUTA1; INSTANCENAME: INS4712; MAKER: MAC8; PARTNAME: HK-2_M8
TP39 = TP: COMP: PRT_44; COMPONENTNAME: TP_TP.Normal_package; FUNCTION: TP_TP.Normal_package; ID: OUTB1; INSTANCENAME: INS4704; MAKER: MAC8; PARTNAME: HK-2_M8
U?#4 = WAKU_DEF100: DATE: 2021-01-27; DRAWINGNUMBER: RD171-SCHEMATIC-01; FUNCTION: PSFB - Primary Bridge; REVISION: 01; SAVEAREA0: 168739,-66042,466246,90057; SAVECOUNT: 5; SHEETNUMBER: 4/8; TITLE: 1.6kW 48V Output Telecomunication / Equipment Power Supply; UPDATEDATE: 2021/01/27; UPDATETIME: 15:56:17

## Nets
VCC12R0_1: R122.1 R123.1 ; also on sheet 1 6 7 8
CONN002: C19.1 D24.A IC4.11 Q3.S Q4.D R31.1 ; also on sheet 4
CONN003: D18.C D19.A L3.2 ; also on sheet 4
CS: D14.C ; also on sheet 3
LGND: R9.1 T4.3 ; also on sheet 1 2 3 4 8
OUTA1: R111.1 ; also on sheet 2
OUTB1: R110.1 ; also on sheet 2
OUTC1: R113.1 ; also on sheet 2
OUTD1: R112.1 ; also on sheet 2
PFC_OUT: R178.2 T4.2 ; also on sheet 1 6 7
PN: C53.1 C54.1 C55.1 C56.1 C57.1 C58.1 C84.1 C85.1 C86.1 C87.1 C103.1 D18.A D22.A D25.A IC4.3 IC4.5 IC5.3 IC5.5 Q4.S Q6.S R29.1 R33.1 R179.1 ; also on sheet 1 2 6 7 8
SIG65: C19.2 D17.C IC4.13
SIG75: C18.2 D16.C IC5.13
SIG82: Q6.G R29.2 R136.2 R137.2
SIG89: C54.2 IC5.1 R111.2 TP38.1
SIG90: C53.2 IC5.2 R110.2 TP39.1
SIG91: C58.2 C84.2 C85.2 IC4.7 R115.1 R122.2
SIG92: D17.A R115.2
SIG93: C57.2 IC4.1 R113.2 TP9.1
SIG94: C56.2 IC4.2 R112.2 TP10.1
SIG95: D16.A R114.2
SIG205: Q4.G R33.2 R134.2 R135.2 TP12.1
SIG206: Q3.G R31.2 R126.2 R127.2 TP11.1
SIG249: C18.1 D23.A IC5.11 L3.1 Q5.S Q6.D R28.1 TP15.1
SIGN269: D23.C D42.A D43.C IC5.12
SIGN270: C55.2 C86.2 C87.2 IC5.7 R114.1 R123.2
SIGN271: R178.1 R179.2
SIGN318: D24.C D40.A D41.C IC4.12
SIGN322: D22.C D46.A D47.C IC5.6
SIGN325: D25.C D44.A D45.C IC4.6
SIGN355: C103.2 D19.C Q3.D Q5.D T4.1
SIGN356: D14.A R9.2 T4.5(4)
N05004: Q5.G R28.2 R132.2 R133.2
N05741: D47.A R137.1
N05742: D43.A R133.1
N05743: D46.C R136.1
N05744: D42.C R132.1
N05745: D45.A R135.1
N05746: D41.A R127.1
N05747: D40.C R126.1
N05748: D44.C R134.1

Not connected (* = marked no-connect by the designer): D22 NC; D23 NC; D24 NC; D25 NC; IC4 4 8 9 10 14; IC5 4 8 9 10 14; T4 4 6 7

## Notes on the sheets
sheet 5
- 1608
- 6432
- 6432
- 1608
- 3225
- 1608
- 3225
- 3216
- 3216
- 3216
- 3216
- 1608
- 1608
- 1005
- 1005
- 1608
- 1608
- 1608
- 1608
- 3216
- 3216
- 1608
- 3216
- 3216
- 1608
- 1608
- 1608
- 3216
- 3216
- 3216
- 1005
- 3216
- 1005
- 1608
- 1608
